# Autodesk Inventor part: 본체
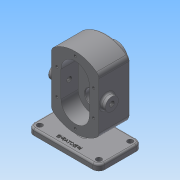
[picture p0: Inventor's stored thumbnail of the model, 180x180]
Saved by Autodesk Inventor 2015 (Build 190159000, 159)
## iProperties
Created: 2019-03
Part Number: 본체
Material: 일반
Document SubType Name: Modeling
Designer: user
Density: 1 g/cm^3
Appearance: 기본값
Author: user
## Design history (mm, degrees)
sketch "스케치2"
  geometry: L1 (-60, -36.5)-(60, -36.5); L2 (60, -36.5)-(60, 36.5); L3 (60, 36.5)-(-60, 36.5); L4 (-60, 36.5)-(-60, -36.5); L5 (-60, -36.5)-(60, 36.5); L6 (60, -36.5)-(-60, 36.5); 1 further point
  constraints: 12 end point, 2 midpoint, 2 parallel, 1 horizontal, 1 perpendicular
  dimensions: "d0" = 120 distance of L3.end L2.end; "d1" = 73 distance of L2.end L1.end
extrude "돌출1" new body sketch "스케치2" distance "d2" = 10; taper "d3" = 0 deg
fillet "모깎기1" dims "d4" = 10
sketch "스케치3"
  geometry: A1 r 10 centre (-50, -26.5) between (-60, -26.5) and (-50, -36.5) reference; A2 r 10 centre (50, -26.5) between (50, -36.5) and (60, -26.5) reference; A3 r 10 centre (50, 26.5) between (60, 26.5) and (50, 36.5) reference; A4 r 10 centre (-50, 26.5) between (-50, 36.5) and (-60, 26.5) reference; 1 further point
hole "구멍1" sketch "스케치3" at (50, -26.5), (50, 26.5), (-50, 26.5), (-50, -26.5) diameter "d5" = 9; stored, may be unused: countersink angle "d9" = 90 deg, drill point angle "d11" = 0 deg; dims "d6" = 6, "d7" = 4, "d8" = 2, "d10" = 8
node "작업 평면1"
sketch "스케치4"
  geometry: L1 (-100, -10)-(0, -10) reference; L2 (-90, 68)-(-10, 68); L3 (-90, 68)-(-90, 112.721); L4 (-10, 68)-(-10, 112.721); L5 (-90, 68)-(-90, 23.279); L6 (-10, 68)-(-10, 23.279); A1 r 60 centre (-50, 68) between (-10, 112.721) and (-90, 112.721); A2 r 60 centre (-50, 68) between (-90, 23.279) and (-10, 23.279); 2 further points
  constraints: 10 end point, 4 point on circle, 2 centre point, 2 symmetric about line, 2 vertical, 1 coincident, 1 horizontal, 1 midpoint, 1 vertical alignment, 1 other
  dimensions: "d22" = 80 distance of L2.start L2.end; "d23" = 78 distance between parallel lines of L1 L2; "d24" = 60 radius of A1; "d25" = 138 dimension on A1 L1 (derived)
extrude "돌출2" join sketch "스케치4" distance "d26" = 53; taper "d27" = 0 deg
sketch "스케치6"
  geometry: L1 (-50, 90)-(-50, 46); L2 (-74, 90)-(-74, 46); L3 (-26, 46)-(-26, 90); A1 r 60 centre (-50, 68) between (-90, 23.279) and (-10, 23.279) reference; A2 r 24 centre (-50, 90) between (-26, 90) and (-74, 90); A3 r 24 centre (-50, 46) between (-74, 46) and (-26, 46); 2 further points
  constraints: 8 end point, 4 point on circle, 4 tangent, 2 centre point, 1 coincident, 1 midpoint, 1 parallel, 1 vertical
  dimensions: "d28" = 48 diameter of A3; "d29" = 44 distance of L1.start L1.end
extrude "돌출3" cut sketch "스케치6" distance "d30" = 29; taper "d31" = 0 deg
sketch "스케치7"
  geometry: C1 r 12.5 at (-50, 46); C2 r 12.5 at (-50, 90); A1 r 24 centre (-50, 46) between (-74, 46) and (-26, 46) reference; A2 r 24 centre (-50, 90) between (-26, 90) and (-74, 90) reference; 1 further point
  constraints: 2 centre point, 2 coincident
  dimensions: "d32" = 25 diameter of C1; "d33" = 25 diameter of C2
extrude "돌출4" cut sketch "스케치7" distance "d34" = 15; taper "d35" = 0 deg
sketch "스케치14"
  geometry: C1 r 12.5 at (50, 90) reference; C2 r 19 at (50, 90); 1 further point
  constraints: 1 centre point, 1 coincident
  dimensions: "d53" = 38 diameter of C2
extrude "돌출8" join sketch "스케치14" distance "d54" = 17; taper "d55" = 0 deg
sketch "스케치15"
  geometry: C1 r 12.5 at (0, 0) reference; C2 r 8.5 at (0, 0); 1 further point
  constraints: 1 centre point, 1 coincident
  dimensions: "d56" = 17 diameter of C2
extrude "돌출9" cut sketch "스케치15" stored distance "d57" = 17; taper "d58" = 0 deg
sketch "스케치16"
  geometry: C1 r 19 at (0, 0) reference; C2 r 14 at (0, 0); 1 further point
  constraints: 1 centre point, 1 coincident
  dimensions: "d60" = 28 diameter of C2
extrude "돌출10" cut sketch "스케치16" distance "d61" = 7.3; taper "d62" = 0 deg
fillet "모깎기4" dims "d63" = 0.5
sketch "스케치18"
  geometry: L1 (50, 36.5)-(-50, 36.5) reference; L2 (-6, 36.5)-(6, 36.5); L3 (6, 36.5)-(6, -6.5); L4 (6, -6.5)-(-6, -6.5); L5 (-6, -6.5)-(-6, 36.5); 2 further points
  constraints: 8 end point, 1 collinear, 1 horizontal, 1 midpoint, 1 perpendicular, 1 vertical, 1 vertical alignment
  dimensions: "d68" = 12 distance of L2.start L2.end; "d69" = 43 distance of L2.end L3.end; "d70" = 12 distance of L3.end L4.end
extrude "돌출11" join sketch "스케치18" stored distance "d71" = 43; taper "d72" = 0 deg
sketch "스케치19"
  geometry: L1 (-50, 90)-(-50, 46); L2 (-81, 90)-(-81, 46); L3 (-19, 46)-(-19, 90); A1 r 24 centre (-50, 46) between (-74, 46) and (-26, 46) reference; A2 r 24 centre (-50, 90) between (-26, 90) and (-74, 90) reference; A3 r 60 centre (-50, 68) between (-10, 112.721) and (-90, 112.721) reference; A4 r 31 centre (-50, 90) between (-19, 90) and (-81, 90); A5 r 31 centre (-50, 46) between (-81, 46) and (-19, 46); 8 further points
  constraints: 10 point on circle, 8 end point, 4 tangent, 2 centre point, 2 horizontal alignment, 1 midpoint, 1 parallel, 1 vertical, 1 vertical alignment
  dimensions: "d73" = 62 diameter of A5; "d74" = 22 vertical distance of point (-19, 90) A3.centre; "d75" = 44 distance of point (-19, 46) point (-19, 90)
hole "구멍2" sketch "스케치19" at (-50, 121), (-50, 15), (-19, 90), (-19, 46), (-81, 90), (-81, 46) diameter "d76" = 4.134; stored, may be unused: countersink angle "d80" = 90 deg, drill point angle "d82" = 118 deg; dims "d77" = 10, "d78" = 4, "d79" = 2, "d81" = 12
fillet "모깎기5" dims "d83" = 10
sketch "스케치20"
  geometry: L1 (0, 0)-(0, 80) reference; L2 (43, -38)-(-10, -38) reference; C1 r 11 at (14, 40); 1 further point
  constraints: 1 centre point
  dimensions: "d84" = 22 diameter of C1; "d85" = 14 distance from line of C1.centre L1; "d86" = 78 distance from line of L2 C1.centre
extrude "돌출12" join sketch "스케치20" distance "d87" = 8; taper "d88" = 0 deg
sketch "스케치21"
  geometry: C1 r 11 at (0, 0) reference; 1 further point
hole "구멍3" sketch "스케치21" at (0, 0) diameter "d89" = 8.376; stored, may be unused: countersink angle "d93" = 90 deg, drill point angle "d95" = 118 deg; dims "d90" = 20, "d91" = 4, "d92" = 2, "d94" = 27.3
sketch "스케치22"
  geometry: C1 r 11 at (0, 0) reference; 1 further point
hole "구멍4" sketch "스케치22" at (0, 0) diameter "d96" = 8.376; stored, may be unused: countersink angle "d100" = 90 deg, drill point angle "d102" = 118 deg; dims "d97" = 20, "d98" = 4, "d99" = 2, "d101" = 27.3
fillet "모깎기6" dims "d103" = 3
fillet "모깎기7" dims "d104" = 3
fillet "모깎기8" dims "d105" = 3
fillet "모깎기9" dims "d106" = 3
fillet "모깎기10" dims "d107" = 3
sketch "스케치23"
  geometry: L1 (-20.739, -23.498)-(20.739, -23.498); L2 (20.739, -23.498)-(20.739, -29.502); L3 (20.739, -29.502)-(-20.739, -29.502); L4 (-20.739, -29.502)-(-20.739, -23.498); L5 (-20.739, -26.5)-(20.739, -26.5); L6 (0, -29.502)-(0, -23.498); L7 (-60, 26.5)-(-60, -26.5) reference; L8 (-50, -36.5)-(50, -36.5) reference; 1 further point
  constraints: 4 end point, 4 midpoint, 2 other
  dimensions: "d108" = 60 distance between parallel lines of L6 L7; "d109" = 10 distance between parallel lines of L5 L8
feature "엠보싱1" sketch "스케치23" dims "d0" = 120, "d1" = 73, "d110" = 0.5, "d111" = 0
sketch "스케치24"
  geometry: 1 further point
chamfer "모따기4" distance "d112" = 1; stored, may be unused: second distance "d113" = 2, angle "d114" = 45 deg
chamfer "모따기5" distance "d116" = 0.7; stored, may be unused: second distance "d117" = 2, angle "d118" = 30 deg
node "솔리드1"
mirror "대칭1"
node "투영된 루프2"
other parameters: "d12" = -53
